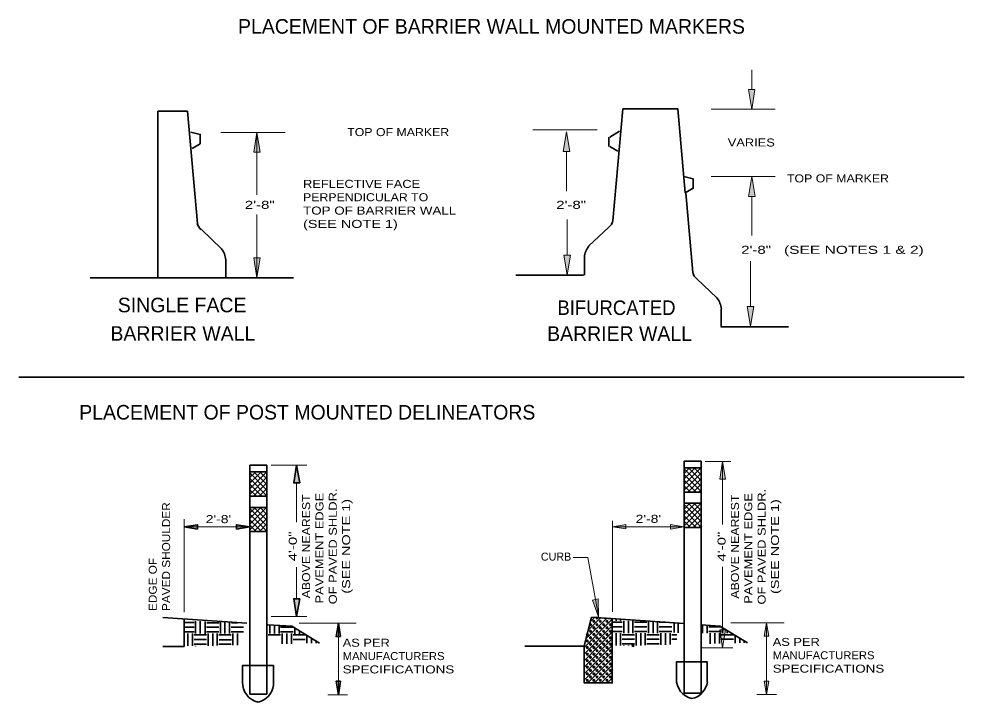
# Model space of a CAD drawing. Extents: x 2147527.1 to 2147534.3, y 2147768.5 to 2147778.6.
# Drawn here: x 2147527.19 to 2147534.27, y 2147773.43 to 2147778.55 of the extents above; entities that cross this region are included whole.
import ezdxf
from ezdxf.enums import TextEntityAlignment as Align

# ---------------------------------------------------------------- set-up
doc = ezdxf.new("R2010")
doc.units = 0
doc.header["$LTSCALE"] = 0.024
doc.header["$PDMODE"] = 32
doc.header["$PDSIZE"] = 0.012
for name, color, linetype, lineweight in [('1', 7, 'Continuous', 35), ('10', 7, 'Continuous', 13), ('63', 7, 'Continuous', 35)]:
    doc.layers.add(name, color=color, linetype=linetype, lineweight=lineweight)
doc.layers.add('12', color=7, linetype='Continuous')
doc.layers.add('13', color=7, linetype='Continuous')

msp = doc.modelspace()

# ---------------------------------------------------------------- hatches: boundary and pattern name
at = {"layer": '10'}
for points in [[(2147532.659, 2147778.022), (2147532.708, 2147778.022), (2147532.684, 2147777.873)], [(2147529.001, 2147777.552), (2147528.952, 2147777.552), (2147528.976, 2147777.7)], [(2147531.271, 2147777.557), (2147531.32, 2147777.557), (2147531.295, 2147777.705)], [(2147532.71, 2147777.22), (2147532.66, 2147777.22), (2147532.685, 2147777.369)], [(2147531.325, 2147776.781), (2147531.275, 2147776.781), (2147531.3, 2147776.633)], [(2147529.001, 2147776.76), (2147528.952, 2147776.76), (2147528.976, 2147776.612)], [(2147532.699, 2147776.397), (2147532.65, 2147776.397), (2147532.674, 2147776.248)], [(2147529.297, 2147775.075), (2147529.252, 2147775.075), (2147529.274, 2147775.208)], [(2147532.488, 2147775.102), (2147532.444, 2147775.102), (2147532.466, 2147775.236)], [(2147528.532, 2147774.728), (2147528.532, 2147774.762), (2147528.432, 2147774.745)], [(2147528.823, 2147774.728), (2147528.823, 2147774.762), (2147528.923, 2147774.745)], [(2147531.74, 2147774.73), (2147531.74, 2147774.764), (2147531.64, 2147774.747)], [(2147532.076, 2147774.729), (2147532.076, 2147774.763), (2147532.176, 2147774.746)], [(2147529.297, 2147774.208), (2147529.252, 2147774.208), (2147529.274, 2147774.075)], [(2147531.491, 2147774.198), (2147531.534, 2147774.206), (2147531.536, 2147774.071)], [(2147529.603, 2147773.924), (2147529.57, 2147773.924), (2147529.587, 2147774.024)], [(2147532.811, 2147773.926), (2147532.778, 2147773.926), (2147532.794, 2147774.026)], [(2147532.488, 2147773.974), (2147532.444, 2147773.974), (2147532.466, 2147773.84)], [(2147529.603, 2147773.589), (2147529.57, 2147773.589), (2147529.587, 2147773.489)], [(2147532.811, 2147773.591), (2147532.778, 2147773.591), (2147532.794, 2147773.491)]]:
    msp.add_hatch(color=256, dxfattribs=at).paths.add_polyline_path(points)

# ---------------------------------------------------------------- linework, layer by layer
at = {"layer": '1'}
for p, q in [((2147528.455, 2147777.859), (2147528.53, 2147777.019)), ((2147531.718, 2147777.878), (2147531.643, 2147777.037)), ((2147531.932, 2147777.878), (2147531.718, 2147777.878)), ((2147531.62, 2147777.664), (2147531.693, 2147777.71)), ((2147531.613, 2147777.664), (2147531.613, 2147777.594)), ((2147531.62, 2147777.594), (2147531.68, 2147777.559)), ((2147532.189, 2147777.249), (2147532.242, 2147776.65)), ((2147531.613, 2147776.991), (2147531.462, 2147776.848)), ((2147528.56, 2147776.972), (2147528.711, 2147776.829)), ((2147528.743, 2147776.611), (2147528.743, 2147776.746)), ((2147531.43, 2147776.63), (2147531.43, 2147776.765)), ((2147528.235, 2147776.612), (2147527.727, 2147776.612)), ((2147532.272, 2147776.604), (2147532.423, 2147776.461)), ((2147532.456, 2147776.244), (2147532.456, 2147776.378)), ((2147532.177, 2147775.238), (2147532.177, 2147773.501)), ((2147532.305, 2147775.238), (2147532.177, 2147775.238)), ((2147532.305, 2147773.501), (2147532.305, 2147775.238)), ((2147528.923, 2147775.207), (2147528.923, 2147773.492)), ((2147529.051, 2147775.207), (2147528.923, 2147775.207)), ((2147529.051, 2147775.157), (2147528.923, 2147775.157)), ((2147528.925, 2147775.034), (2147529.046, 2147775.154)), ((2147528.925, 2147775.076), (2147529.004, 2147775.154)), ((2147528.925, 2147775.117), (2147528.962, 2147775.154)), ((2147529.048, 2147775.023), (2147528.925, 2147775.147)), ((2147529.048, 2147775.065), (2147528.959, 2147775.154)), ((2147529.048, 2147775.107), (2147529.002, 2147775.154)), ((2147529.048, 2147775.15), (2147529.044, 2147775.154)), ((2147529.051, 2147773.492), (2147529.051, 2147775.207)), ((2147532.305, 2147775.188), (2147532.177, 2147775.188)), ((2147532.179, 2147775.065), (2147532.3, 2147775.185)), ((2147532.179, 2147775.107), (2147532.258, 2147775.185)), ((2147532.179, 2147775.148), (2147532.216, 2147775.185)), ((2147532.302, 2147775.054), (2147532.179, 2147775.178)), ((2147532.179, 2147775.023), (2147532.302, 2147775.146)), ((2147532.302, 2147775.096), (2147532.213, 2147775.185)), ((2147532.302, 2147775.138), (2147532.256, 2147775.185)), ((2147532.302, 2147775.181), (2147532.298, 2147775.185)), ((2147528.925, 2147774.992), (2147529.048, 2147775.115)), ((2147529.048, 2147774.982), (2147528.925, 2147775.105)), ((2147528.955, 2147774.98), (2147529.048, 2147775.073)), ((2147532.302, 2147775.013), (2147532.179, 2147775.136)), ((2147532.263, 2147775.011), (2147532.179, 2147775.093)), ((2147532.209, 2147775.011), (2147532.302, 2147775.104)), ((2147529.009, 2147774.98), (2147528.925, 2147775.062)), ((2147528.967, 2147774.98), (2147528.925, 2147775.02)), ((2147528.997, 2147774.98), (2147529.048, 2147775.031)), ((2147532.305, 2147775.006), (2147532.177, 2147775.006)), ((2147532.221, 2147775.011), (2147532.179, 2147775.051)), ((2147532.251, 2147775.011), (2147532.302, 2147775.062)), ((2147532.293, 2147775.011), (2147532.302, 2147775.02)), ((2147529.051, 2147774.975), (2147528.923, 2147774.975)), ((2147529.039, 2147774.98), (2147529.048, 2147774.989)), ((2147529.051, 2147774.892), (2147528.923, 2147774.892)), ((2147528.925, 2147774.768), (2147529.046, 2147774.888)), ((2147528.925, 2147774.81), (2147529.004, 2147774.888)), ((2147528.925, 2147774.851), (2147528.962, 2147774.888)), ((2147529.048, 2147774.757), (2147528.925, 2147774.881)), ((2147529.048, 2147774.799), (2147528.959, 2147774.888)), ((2147529.048, 2147774.841), (2147529.002, 2147774.888)), ((2147529.048, 2147774.884), (2147529.044, 2147774.888)), ((2147532.305, 2147774.923), (2147532.177, 2147774.923)), ((2147532.179, 2147774.799), (2147532.3, 2147774.919)), ((2147532.179, 2147774.841), (2147532.258, 2147774.919)), ((2147532.179, 2147774.882), (2147532.216, 2147774.919)), ((2147532.302, 2147774.788), (2147532.179, 2147774.912)), ((2147532.179, 2147774.757), (2147532.302, 2147774.88)), ((2147532.302, 2147774.747), (2147532.179, 2147774.87)), ((2147532.302, 2147774.83), (2147532.213, 2147774.919)), ((2147532.302, 2147774.872), (2147532.256, 2147774.919)), ((2147532.302, 2147774.915), (2147532.298, 2147774.919)), ((2147528.925, 2147774.726), (2147529.048, 2147774.849)), ((2147529.048, 2147774.716), (2147528.925, 2147774.839)), ((2147529.009, 2147774.714), (2147528.925, 2147774.796)), ((2147528.955, 2147774.714), (2147529.048, 2147774.807)), ((2147532.263, 2147774.745), (2147532.179, 2147774.827)), ((2147532.221, 2147774.745), (2147532.179, 2147774.786)), ((2147532.209, 2147774.745), (2147532.302, 2147774.838)), ((2147532.251, 2147774.745), (2147532.302, 2147774.796)), ((2147528.967, 2147774.714), (2147528.925, 2147774.755)), ((2147528.997, 2147774.714), (2147529.048, 2147774.765)), ((2147529.039, 2147774.714), (2147529.048, 2147774.723)), ((2147532.305, 2147774.741), (2147532.177, 2147774.741)), ((2147532.293, 2147774.745), (2147532.302, 2147774.754)), ((2147529.051, 2147774.71), (2147528.923, 2147774.71)), ((2147528.271, 2147774.067), (2147528.902, 2147774.024)), ((2147528.431, 2147774.029), (2147528.505, 2147774.029)), ((2147528.517, 2147773.947), (2147528.517, 2147774.04)), ((2147528.552, 2147773.947), (2147528.552, 2147774.04)), ((2147528.588, 2147773.945), (2147528.588, 2147774.038)), ((2147528.6, 2147774.027), (2147528.693, 2147774.027)), ((2147528.703, 2147773.947), (2147528.703, 2147774.038)), ((2147528.737, 2147773.947), (2147528.737, 2147774.035)), ((2147528.771, 2147773.947), (2147528.771, 2147774.033)), ((2147528.785, 2147774.027), (2147528.831, 2147774.027)), ((2147529.058, 2147774.013), (2147529.238, 2147774.001)), ((2147529.073, 2147773.947), (2147529.073, 2147774.012)), ((2147529.108, 2147773.947), (2147529.108, 2147774.01)), ((2147529.142, 2147773.947), (2147529.142, 2147774.007)), ((2147531.43, 2147773.844), (2147531.639, 2147774.054)), ((2147531.43, 2147773.795), (2147531.639, 2147774.004)), ((2147531.442, 2147773.907), (2147531.597, 2147774.062)), ((2147531.459, 2147773.973), (2147531.551, 2147774.064)), ((2147531.476, 2147774.038), (2147531.505, 2147774.067)), ((2147531.484, 2147774.069), (2147532.177, 2147774.021)), ((2147531.484, 2147774.069), (2147531.639, 2147774.058)), ((2147531.639, 2147774.058), (2147531.639, 2147773.853)), ((2147531.639, 2147774.031), (2147531.713, 2147774.031)), ((2147531.667, 2147774.042), (2147531.667, 2147774.056)), ((2147531.701, 2147774.042), (2147531.701, 2147774.054)), ((2147531.725, 2147773.95), (2147531.725, 2147774.042)), ((2147531.76, 2147773.95), (2147531.76, 2147774.042)), ((2147531.794, 2147773.95), (2147531.794, 2147774.042)), ((2147531.806, 2147774.031), (2147531.898, 2147774.031)), ((2147531.818, 2147774.042), (2147531.818, 2147774.046)), ((2147531.852, 2147774.042), (2147531.852, 2147774.044)), ((2147531.91, 2147773.95), (2147531.91, 2147774.04)), ((2147531.945, 2147773.95), (2147531.945, 2147774.037)), ((2147531.979, 2147773.95), (2147531.979, 2147774.035)), ((2147531.991, 2147774.031), (2147532.037, 2147774.031)), ((2147532.103, 2147773.955), (2147532.103, 2147774.026)), ((2147532.132, 2147773.951), (2147532.132, 2147774.024)), ((2147532.305, 2147774.012), (2147532.445, 2147774.003)), ((2147532.316, 2147773.95), (2147532.316, 2147774.012)), ((2147532.35, 2147773.95), (2147532.35, 2147774.009)), ((2147528.431, 2147773.994), (2147528.505, 2147773.994)), ((2147528.431, 2147773.959), (2147528.505, 2147773.959)), ((2147528.459, 2147773.855), (2147528.459, 2147773.947)), ((2147528.493, 2147773.855), (2147528.493, 2147773.947)), ((2147528.505, 2147773.936), (2147528.598, 2147773.936)), ((2147528.598, 2147773.994), (2147528.691, 2147773.994)), ((2147528.598, 2147773.959), (2147528.691, 2147773.959)), ((2147528.61, 2147773.856), (2147528.61, 2147773.947)), ((2147528.645, 2147773.856), (2147528.645, 2147773.947)), ((2147528.679, 2147773.857), (2147528.679, 2147773.947)), ((2147528.691, 2147773.936), (2147528.783, 2147773.936)), ((2147528.783, 2147773.994), (2147528.876, 2147773.994)), ((2147528.783, 2147773.959), (2147528.876, 2147773.959)), ((2147528.795, 2147773.86), (2147528.795, 2147773.947)), ((2147528.83, 2147773.861), (2147528.83, 2147773.947)), ((2147529.061, 2147773.936), (2147529.154, 2147773.936)), ((2147529.154, 2147773.994), (2147529.247, 2147773.994)), ((2147529.154, 2147773.959), (2147529.247, 2147773.959)), ((2147529.166, 2147773.869), (2147529.166, 2147773.947)), ((2147529.201, 2147773.87), (2147529.201, 2147773.947)), ((2147529.235, 2147773.871), (2147529.235, 2147773.947)), ((2147529.238, 2147774.001), (2147529.446, 2147773.876)), ((2147529.247, 2147773.936), (2147529.339, 2147773.936)), ((2147529.26, 2147773.945), (2147529.26, 2147773.986)), ((2147529.295, 2147773.945), (2147529.295, 2147773.965)), ((2147529.351, 2147773.874), (2147529.351, 2147773.933)), ((2147531.43, 2147773.746), (2147531.639, 2147773.956)), ((2147531.639, 2147773.996), (2147531.713, 2147773.996)), ((2147531.639, 2147773.961), (2147531.713, 2147773.961)), ((2147531.667, 2147773.857), (2147531.667, 2147773.95)), ((2147531.701, 2147773.857), (2147531.701, 2147773.95)), ((2147531.713, 2147773.938), (2147531.806, 2147773.938)), ((2147531.806, 2147773.996), (2147531.898, 2147773.996)), ((2147531.806, 2147773.961), (2147531.898, 2147773.961)), ((2147531.818, 2147773.858), (2147531.818, 2147773.95)), ((2147531.852, 2147773.858), (2147531.852, 2147773.95)), ((2147531.886, 2147773.859), (2147531.886, 2147773.95)), ((2147531.898, 2147773.938), (2147531.991, 2147773.938)), ((2147531.991, 2147773.996), (2147532.084, 2147773.996)), ((2147531.991, 2147773.961), (2147532.084, 2147773.961)), ((2147532.003, 2147773.862), (2147532.003, 2147773.95)), ((2147532.038, 2147773.863), (2147532.038, 2147773.95)), ((2147532.072, 2147773.864), (2147532.072, 2147773.95)), ((2147532.084, 2147773.938), (2147532.123, 2147773.938)), ((2147532.362, 2147773.996), (2147532.454, 2147773.996)), ((2147532.362, 2147773.961), (2147532.454, 2147773.961)), ((2147532.373, 2147773.871), (2147532.373, 2147773.95)), ((2147532.408, 2147773.873), (2147532.408, 2147773.95)), ((2147532.442, 2147773.873), (2147532.442, 2147773.95)), ((2147532.445, 2147774.003), (2147532.653, 2147773.878)), ((2147532.454, 2147773.938), (2147532.547, 2147773.938)), ((2147532.466, 2147773.95), (2147532.466, 2147773.99)), ((2147532.501, 2147773.95), (2147532.501, 2147773.97)), ((2147532.559, 2147773.876), (2147532.559, 2147773.935)), ((2147528.505, 2147773.901), (2147528.598, 2147773.901)), ((2147528.505, 2147773.867), (2147528.598, 2147773.867)), ((2147528.691, 2147773.867), (2147528.783, 2147773.867)), ((2147528.693, 2147773.899), (2147528.785, 2147773.899)), ((2147529.247, 2147773.901), (2147529.339, 2147773.901)), ((2147529.386, 2147773.875), (2147529.386, 2147773.912)), ((2147529.42, 2147773.876), (2147529.42, 2147773.891)), ((2147531.43, 2147773.697), (2147531.639, 2147773.907)), ((2147531.713, 2147773.904), (2147531.806, 2147773.904)), ((2147531.713, 2147773.869), (2147531.806, 2147773.869)), ((2147531.898, 2147773.904), (2147531.991, 2147773.904)), ((2147531.898, 2147773.869), (2147531.991, 2147773.869)), ((2147532.084, 2147773.904), (2147532.123, 2147773.904)), ((2147532.454, 2147773.904), (2147532.547, 2147773.904)), ((2147532.594, 2147773.877), (2147532.594, 2147773.914)), ((2147532.628, 2147773.878), (2147532.628, 2147773.893)), ((2147528.517, 2147773.853), (2147528.517, 2147773.855)), ((2147528.552, 2147773.854), (2147528.552, 2147773.855)), ((2147531.43, 2147773.648), (2147531.639, 2147773.857)), ((2147531.43, 2147773.599), (2147531.639, 2147773.809)), ((2147531.725, 2147773.855), (2147531.725, 2147773.857)), ((2147531.76, 2147773.856), (2147531.76, 2147773.857)), ((2147531.456, 2147773.577), (2147531.639, 2147773.759)), ((2147531.505, 2147773.577), (2147531.639, 2147773.71)), ((2147531.555, 2147773.577), (2147531.639, 2147773.661)), ((2147531.604, 2147773.577), (2147531.639, 2147773.612)), ((2147528.923, 2147773.492), (2147529.051, 2147773.492)), ((2147532.177, 2147773.501), (2147532.305, 2147773.501))]:
    msp.add_line(p, q, dxfattribs=at)
for points in [[(2147528.235, 2147776.612), (2147528.235, 2147777.859), (2147528.455, 2147777.859)], [(2147531.932, 2147777.878), (2147532.13, 2147777.878), (2147532.186, 2147777.247)], [(2147528.481, 2147777.703), (2147528.552, 2147777.685), (2147528.552, 2147777.615), (2147528.492, 2147777.58)], [(2147532.175, 2147777.37), (2147532.246, 2147777.352), (2147532.246, 2147777.282), (2147532.186, 2147777.247)], [(2147528.431, 2147774.056), (2147528.431, 2147773.851), (2147528.271, 2147773.851)], [(2147531.484, 2147774.069), (2147531.429, 2147773.855), (2147531.429, 2147773.577), (2147531.639, 2147773.577), (2147531.639, 2147773.855)], [(2147532.12, 2147773.61), (2147532.12, 2147773.734), (2147532.351, 2147773.734), (2147532.351, 2147773.585)], [(2147528.869, 2147773.584), (2147528.869, 2147773.708), (2147529.1, 2147773.708), (2147529.1, 2147773.559)]]:
    msp.add_lwpolyline(points, dxfattribs=at)
for centre, radius, start, end in [((2147528.6129, 2147777.0395), 0.0858, 194.04109, 231.79025), ((2147531.5601, 2147777.0575), 0.0858, 308.20975, 345.95891), ((2147531.5838, 2147776.752), 0.1547, 141.70342, 175.12637), ((2147528.5891, 2147776.733), 0.1547, 4.87363, 38.29658), ((2147532.3257, 2147776.6708), 0.0858, 194.04109, 231.79025), ((2147532.302, 2147776.3653), 0.1547, 4.87363, 38.29658), ((2147529.0168, 2147773.5779), 0.1479, 177.67867, 257.64302), ((2147532.2678, 2147773.6039), 0.1479, 177.67867, 257.64302), ((2147532.2045, 2147773.6039), 0.1479, 282.35698, 352.77958), ((2147528.9535, 2147773.5779), 0.1479, 282.35698, 352.77958)]:
    msp.add_arc(centre, radius, start, end, dxfattribs=at)
for p in [(2147531.476, 2147774.014), (2147531.501, 2147774.039), (2147531.525, 2147774.063), (2147531.525, 2147774.014), (2147531.55, 2147774.039), (2147531.574, 2147774.014), (2147531.599, 2147774.039), (2147531.624, 2147774.014), (2147531.452, 2147773.94), (2147531.476, 2147773.964), (2147531.501, 2147773.99), (2147531.501, 2147773.94), (2147531.525, 2147773.964), (2147531.55, 2147773.99), (2147531.55, 2147773.94), (2147531.574, 2147773.964), (2147531.599, 2147773.99), (2147531.599, 2147773.94), (2147531.624, 2147773.964), (2147531.452, 2147773.891), (2147531.476, 2147773.915), (2147531.476, 2147773.867), (2147531.501, 2147773.891), (2147531.525, 2147773.915), (2147531.525, 2147773.867), (2147531.55, 2147773.891), (2147531.574, 2147773.915), (2147531.574, 2147773.867), (2147531.599, 2147773.891), (2147531.624, 2147773.915), (2147531.624, 2147773.867), (2147531.794, 2147773.857), (2147531.452, 2147773.842), (2147531.452, 2147773.792), (2147531.476, 2147773.818), (2147531.501, 2147773.842), (2147531.501, 2147773.792), (2147531.525, 2147773.818), (2147531.55, 2147773.842), (2147531.55, 2147773.792), (2147531.574, 2147773.818), (2147531.599, 2147773.842), (2147531.599, 2147773.792), (2147531.624, 2147773.818), (2147531.452, 2147773.744), (2147531.476, 2147773.768), (2147531.476, 2147773.719), (2147531.501, 2147773.744), (2147531.525, 2147773.768), (2147531.525, 2147773.719), (2147531.55, 2147773.744), (2147531.574, 2147773.768), (2147531.574, 2147773.719), (2147531.599, 2147773.744), (2147531.624, 2147773.768), (2147531.624, 2147773.719), (2147531.452, 2147773.695), (2147531.452, 2147773.645), (2147531.476, 2147773.67), (2147531.501, 2147773.695), (2147531.501, 2147773.645), (2147531.525, 2147773.67), (2147531.55, 2147773.695), (2147531.55, 2147773.645), (2147531.574, 2147773.67), (2147531.599, 2147773.695), (2147531.599, 2147773.645), (2147531.624, 2147773.67), (2147531.452, 2147773.596), (2147531.476, 2147773.621), (2147531.501, 2147773.596), (2147531.525, 2147773.621), (2147531.55, 2147773.596), (2147531.574, 2147773.621), (2147531.599, 2147773.596), (2147531.624, 2147773.621)]:
    msp.add_point(p, dxfattribs=at)
at = {"layer": '10'}
for p, q in [((2147532.684, 2147778.022), (2147532.684, 2147778.17)), ((2147532.379, 2147777.874), (2147532.859, 2147777.874)), ((2147528.707, 2147777.7), (2147529.188, 2147777.7)), ((2147528.976, 2147777.7), (2147528.976, 2147777.233)), ((2147531.044, 2147777.72), (2147531.525, 2147777.72)), ((2147531.295, 2147777.557), (2147531.295, 2147777.26)), ((2147532.379, 2147777.369), (2147532.859, 2147777.369)), ((2147532.685, 2147777.22), (2147532.685, 2147776.928)), ((2147528.976, 2147777.085), (2147528.976, 2147776.612)), ((2147531.3, 2147776.781), (2147531.3, 2147777.048)), ((2147532.674, 2147776.397), (2147532.674, 2147776.737)), ((2147529.084, 2147775.208), (2147529.351, 2147775.208)), ((2147532.335, 2147775.236), (2147532.528, 2147775.236)), ((2147532.466, 2147775.236), (2147532.466, 2147774.763)), ((2147529.274, 2147775.075), (2147529.274, 2147774.782)), ((2147528.432, 2147774.803), (2147528.432, 2147774.106)), ((2147531.64, 2147774.792), (2147531.64, 2147774.109)), ((2147528.432, 2147774.745), (2147528.923, 2147774.745)), ((2147531.64, 2147774.747), (2147532.177, 2147774.747)), ((2147531.456, 2147774.517), (2147531.346, 2147774.517)), ((2147531.537, 2147774.065), (2147531.456, 2147774.517)), ((2147529.274, 2147774.208), (2147529.274, 2147774.444)), ((2147532.466, 2147773.974), (2147532.466, 2147774.447)), ((2147529.084, 2147774.075), (2147529.351, 2147774.075)), ((2147529.292, 2147774.024), (2147529.72, 2147774.024)), ((2147529.587, 2147774.024), (2147529.587, 2147773.489)), ((2147532.526, 2147774.026), (2147532.928, 2147774.026)), ((2147532.794, 2147774.026), (2147532.794, 2147773.491)), ((2147532.312, 2147773.84), (2147532.542, 2147773.84)), ((2147529.508, 2147773.489), (2147529.656, 2147773.489)), ((2147532.721, 2147773.491), (2147532.869, 2147773.491))]:
    msp.add_line(p, q, dxfattribs=at)
at = {"layer": '10', "lineweight": 35}
for p, q in [((2147530.916, 2147776.632), (2147531.424, 2147776.632)), ((2147529.251, 2147776.612), (2147528.235, 2147776.612)), ((2147532.452, 2147776.244), (2147532.96, 2147776.244)), ((2147531.429, 2147773.853), (2147530.983, 2147773.853))]:
    msp.add_line(p, q, dxfattribs=at)
at = {"layer": '10'}
for points in [[(2147532.659, 2147778.022), (2147532.708, 2147778.022), (2147532.684, 2147777.873)], [(2147529.001, 2147777.552), (2147528.952, 2147777.552), (2147528.976, 2147777.7)], [(2147531.271, 2147777.557), (2147531.32, 2147777.557), (2147531.295, 2147777.705)], [(2147532.71, 2147777.22), (2147532.66, 2147777.22), (2147532.685, 2147777.369)], [(2147531.325, 2147776.781), (2147531.275, 2147776.781), (2147531.3, 2147776.633)], [(2147529.001, 2147776.76), (2147528.952, 2147776.76), (2147528.976, 2147776.612)], [(2147532.699, 2147776.397), (2147532.65, 2147776.397), (2147532.674, 2147776.248)], [(2147532.488, 2147775.102), (2147532.444, 2147775.102), (2147532.466, 2147775.236)], [(2147531.74, 2147774.73), (2147531.74, 2147774.764), (2147531.64, 2147774.747)], [(2147532.076, 2147774.729), (2147532.076, 2147774.763), (2147532.176, 2147774.746)], [(2147531.491, 2147774.198), (2147531.534, 2147774.206), (2147531.536, 2147774.071)], [(2147532.811, 2147773.926), (2147532.778, 2147773.926), (2147532.794, 2147774.026)], [(2147532.488, 2147773.974), (2147532.444, 2147773.974), (2147532.466, 2147773.84)], [(2147532.811, 2147773.591), (2147532.778, 2147773.591), (2147532.794, 2147773.491)]]:
    msp.add_lwpolyline(points, close=True, dxfattribs=at)
at = {"layer": '10', "lineweight": 35}
for points in [[(2147529.297, 2147775.075), (2147529.252, 2147775.075), (2147529.274, 2147775.208)], [(2147528.532, 2147774.728), (2147528.532, 2147774.762), (2147528.432, 2147774.745)], [(2147528.823, 2147774.728), (2147528.823, 2147774.762), (2147528.923, 2147774.745)], [(2147529.297, 2147774.208), (2147529.252, 2147774.208), (2147529.274, 2147774.075)], [(2147529.603, 2147773.924), (2147529.57, 2147773.924), (2147529.587, 2147774.024)], [(2147529.603, 2147773.589), (2147529.57, 2147773.589), (2147529.587, 2147773.489)]]:
    msp.add_lwpolyline(points, close=True, dxfattribs=at)
at = {"layer": '63'}
msp.add_line((2147527.193, 2147775.866), (2147534.275, 2147775.866), dxfattribs=at)

# ---------------------------------------------------------------- texts
at = {"layer": '12'}
for s, p in [('PLACEMENT OF BARRIER WALL MOUNTED MARKERS', (2147528.835, 2147778.44)), ('SINGLE FACE', (2147527.934, 2147776.353)), ('BARRIER WALL', (2147527.879, 2147776.14)), ('BARRIER WALL', (2147531.151, 2147776.139)), ('PLACEMENT OF POST MOUNTED DELINEATORS', (2147527.645, 2147775.55))]:
    msp.add_text(s, height=0.109, dxfattribs=at).set_placement(p)
at = {"layer": '12', "width": 0.95}
msp.add_text('BIFURCATED', height=0.109, dxfattribs=at).set_placement((2147531.228, 2147776.333))
at = {"layer": '13'}
for s, width, p in [('TOP OF MARKER', 1.15, (2147529.653, 2147777.673)), ('VARIES', 1.2, (2147532.504, 2147777.595)), ('REFLECTIVE FACE', 1.2, (2147529.322, 2147777.285)), ('TOP OF MARKER', 1.15, (2147532.948, 2147777.326)), ('PERPENDICULAR TO', 1.15, (2147529.322, 2147777.185)), ('2\'-8"', 1.4, (2147528.886, 2147777.128)), ('TOP OF BARRIER WALL', 1.25, (2147529.322, 2147777.085)), ('2\'-8"', 1.4, (2147531.219, 2147777.128)), ('(SEE NOTE 1)', 1.35, (2147529.322, 2147776.985)), ('2\'-8"', 1.4, (2147532.605, 2147776.791)), ('  (SEE NOTES 1 & 2)', 1.45, (2147532.861, 2147776.791)), ("2'-8'", 1.3, (2147528.593, 2147774.774)), ("2'-8'", 1.3, (2147531.814, 2147774.776)), ('AS PER', 1.2, (2147529.619, 2147773.848)), ('AS PER', 1.2, (2147532.841, 2147773.854)), ('MANUFACTURERS', 1.05, (2147529.619, 2147773.748)), ('MANUFACTURERS', 1.05, (2147532.841, 2147773.754)), ('SPECIFICATIONS', 1.25, (2147529.619, 2147773.648)), ('SPECIFICATIONS', 1.25, (2147532.841, 2147773.654))]:
    msp.add_text(s, height=0.06, dxfattribs=dict(at, width=width)).set_placement(p)
for s, width, p in [('PAVEMENT EDGE ', 1.2, (2147529.475, 2147774.6)), ('OF PAVED SHLDR.', 1.2, (2147529.575, 2147774.5995)), ('OF PAVED SHLDR.', 1.2, (2147532.788, 2147774.5975)), ('ABOVE NEAREST', 1.15, (2147529.375, 2147774.6)), ('(SEE NOTE 1)', 1.35, (2147529.675, 2147774.6)), ('ABOVE NEAREST', 1.15, (2147532.588, 2147774.598)), ('PAVEMENT EDGE ', 1.2, (2147532.688, 2147774.598)), ('(SEE NOTE 1)', 1.35, (2147532.888, 2147774.598)), ('4\'-0"', 1.4, (2147529.275, 2147774.5995)), ('4\'-0"', 1.4, (2147532.488, 2147774.5975))]:
    msp.add_text(s, height=0.06, rotation=90, dxfattribs=dict(at, width=width)).set_placement(p, align=Align.CENTER)
at = {"layer": '13', "width": 1.1}
for s, p in [('PAVED SHOULDER', (2147528.326, 2147774.116)), ('EDGE OF', (2147528.226, 2147774.116))]:
    msp.add_text(s, height=0.06, rotation=90, dxfattribs=at).set_placement(p)
at = {"layer": '13'}
msp.add_text('CURB', height=0.06, dxfattribs=at).set_placement((2147531.104, 2147774.493))

doc.saveas('drawing.dxf')
